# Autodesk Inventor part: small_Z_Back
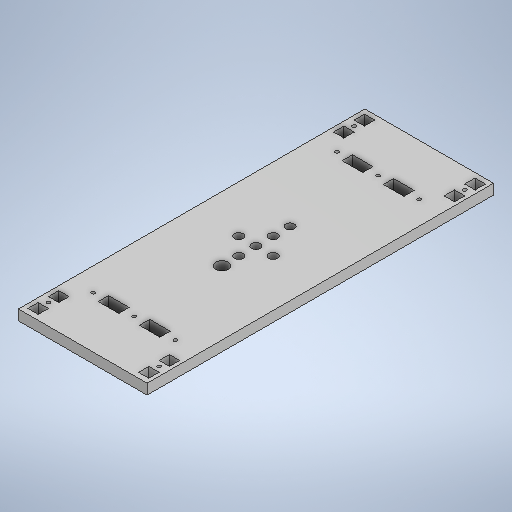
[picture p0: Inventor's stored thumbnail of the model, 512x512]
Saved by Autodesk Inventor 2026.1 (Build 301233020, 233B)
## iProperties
Created: 2026-10
Part Number: small_Z_Back
Material: Steel
Document SubType Name: Modeling
Designer: hp
Density: 7.85 g/cm^3
Appearance: Default
Author: hp
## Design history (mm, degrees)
feature "Body1"
sketch "Sketch1"
  geometry: L1 (19.089, 150.87)-(56.222, 150.87); L2 (56.222, 150.87)-(56.222, 50.004); L3 (56.222, 50.004)-(19.089, 50.004); L4 (19.089, 50.004)-(19.089, 150.87); 1 further point
  constraints: 8 end point, 2 parallel, 1 horizontal, 1 perpendicular
extrude "Extrusion1" join sketch "Sketch1" distance "d0" = 10; taper "d1" = 0 deg
sketch "Sketch2"
  geometry: L1 (0, 0)-(0, 202) reference; L2 (75, 202)-(75, 0) reference; C1 r 1 at (37.5, 172.244) reference; C2 r 2.5 at (37.5, 101); C3 r 2.5 at (37.5, 120.85); C4 r 2.5 at (37.5, 91); C5 r 2.5 at (47.5, 101); C6 r 3.6 at (37.5, 81.15); C7 r 2.5 at (37.5, 111); C8 r 2.5 at (27.5, 101); C9 r 2.5 at (37.5, 101); 4 further points
  constraints: 8 centre point, 5 vertical alignment, 3 horizontal alignment, 2 coincident, 1 concentric, 1 midpoint
  dimensions: "d6" = 5 diameter of C2; "d15" = 5 diameter of C4; "d16" = 5 diameter of C9; "d17" = 10 distance of point (37.5, 101) C5.centre; "d18" = 10 distance of point (37.5, 101) C8.centre; "d19" = 5 diameter of C8; "d20" = 5 diameter of C5; "d21" = 10 distance of point (37.5, 101) C7.centre; "d22" = 5 diameter of C7; "d23" = 7.2 diameter of C6; "d24" = 5 diameter of C3; "d25" = 10 distance of point (37.5, 101) C4.centre; "d26" = 9.85 distance of C7.centre C3.centre; "d27" = 9.85 distance of C4.centre C6.centre
extrude "Extrusion2" cut sketch "Sketch2" extent not by distance; stored distance "d12" = 0; taper "d13" = 0 deg
sketch "Sketch3"
  geometry: C1 r 4.5 at (37.5, -91); C2 r 2.5 at (37.5, -91) reference; C3 r 4.5 at (37.5, -120.85); C4 r 4.5 at (37.5, -111); C5 r 4.5 at (82.635, -97.522); C6 r 2.5 at (37.5, -120.85) reference; C7 r 2.5 at (37.5, -111) reference; 1 further point
  constraints: 4 centre point, 3 concentric
  dimensions: "d28" = 9 diameter of C1; "d29" = 9 diameter of C3; "d30" = 9 diameter of C4; "d31" = 9 diameter of C5
extrude "Extrusion3" cut sketch "Sketch3" stored distance "d32" = 10; taper "d33" = 0 deg
body "Solid1"
